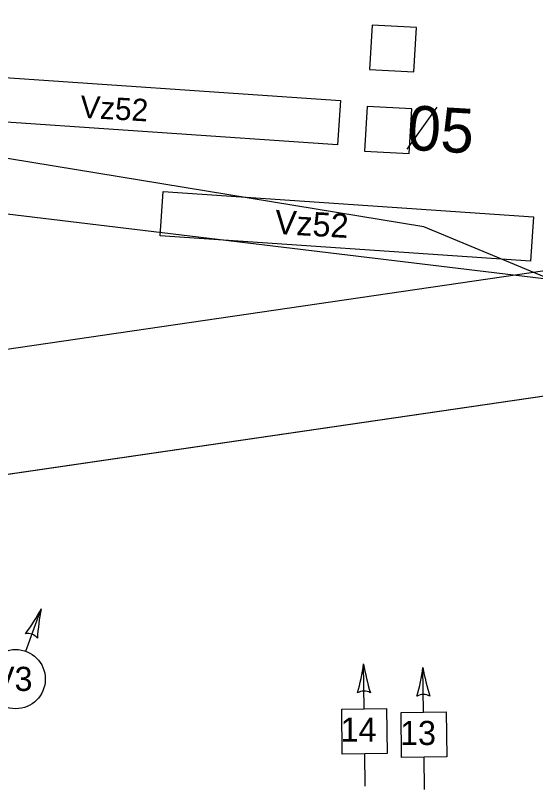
# Model space of a CAD drawing. Extents: x 647787 to 668496, y 640478 to 654412.
# Drawn here: x 661919.8 to 661989.9, y 647240.6 to 647344.9 of the extents above; entities that cross this region are included whole.
import ezdxf

# ---------------------------------------------------------------- set-up
doc = ezdxf.new("R2010")
doc.units = 0
for name, color, linetype in [('Default', 7, 'Continuous'), ('TEMP_DETECTION ZONE', 7, 'Continuous'), ('TEMP_DETECTION_ZONE_STAGE 5', 7, 'Continuous'), ('TEMP_SIGNAL_HEAD_STAGE 2', 7, 'Continuous'), ('TEMP_SIGNAL_POLES_STAGE 1B', 7, 'Continuous'), ('TEXT_TEMP_SIGNAL_POLES_STAGE 2', 7, 'Continuous')]:
    doc.layers.add(name, color=color, linetype=linetype)

msp = doc.modelspace()

# ---------------------------------------------------------------- linework, layer by layer
at = {"layer": 'Default'}
msp.add_line((661972.57, 647326.95), (661976.61, 647332.61), dxfattribs=at)
for points in [[(661974.83, 647316.48), (661742.97, 647354.55)], [(662193.11, 647333.04), (662139.14, 647248.2), (661974.83, 647316.48)], [(662136.44, 647331.77), (661882.02, 647294.61), (661114.4, 647320.89)], [(662008.15, 647307.38), (661891.05, 647321.5)], [(662008.15, 647307.38), (661891.05, 647321.5)], [(662008.15, 647307.38), (661891.05, 647321.5)], [(662108.29, 647310.77), (661853.87, 647273.61), (661086.25, 647299.89)], [(662108.29, 647310.77), (661888.55, 647278.68)], [(662108.29, 647310.77), (661888.55, 647278.68)]]:
    msp.add_lwpolyline(points, dxfattribs=at)
at = {"layer": 'TEMP_DETECTION ZONE'}
for points in [[(661967.86, 647343.64), (661967.5, 647337.65), (661973.5, 647337.34), (661973.86, 647343.33)], [(661967.86, 647343.64), (661967.5, 647337.65), (661973.5, 647337.34), (661973.86, 647343.33)], [(661967.2, 647332.66), (661966.84, 647326.67), (661972.83, 647326.36), (661973.19, 647332.35)], [(661967.2, 647332.66), (661966.84, 647326.67), (661972.83, 647326.36), (661973.19, 647332.35)]]:
    msp.add_lwpolyline(points, close=True, dxfattribs=at)
at = {"layer": 'TEMP_DETECTION_ZONE_STAGE 5'}
msp.add_lwpolyline([(661913.31, 647330.91), (661913.72, 647336.89), (661963.6, 647333.48), (661963.19, 647327.5)], close=True, dxfattribs=at)
at = {"layer": 'TEMP_SIGNAL_HEAD_STAGE 2'}
for p, q in [((661921.2, 647259.28), (661923.28, 647264.98)), ((661966.79, 647251.52), (661966.71, 647257.56)), ((661974.8, 647251.05), (661974.71, 647257.09)), ((661966.93, 647241.11), (661966.87, 647245.46)), ((661974.93, 647240.65), (661974.88, 647244.99))]:
    msp.add_line(p, q, dxfattribs=at)
for points in [[(661969.9, 647245.5), (661963.84, 647245.42), (661963.76, 647251.48), (661969.82, 647251.56)], [(661977.91, 647245.03), (661971.84, 647244.95), (661971.76, 647251.01), (661977.83, 647251.1)]]:
    msp.add_lwpolyline(points, close=True, dxfattribs=at)
msp.add_circle((661919.82, 647255.52), 4, dxfattribs=at)
for centre, radius, start, end in [((661897.42, 647279.11), 29.47, 323.6033, 331.3414), ((661952.16, 647259.13), 29.47, 168.5589, 176.297), ((661921.47, 647260.03), 1.63, 38.0923, 101.7869), ((661937.51, 647261.58), 29.47, 344.421, 352.1591), ((661995.79, 647262.36), 29.47, 189.3758, 197.1139), ((661945.52, 647261.12), 29.47, 344.421, 352.1591), ((662003.79, 647261.9), 29.47, 189.3758, 197.1139), ((661966.78, 647252.29), 1.63, 58.9201, 122.6148), ((661974.79, 647251.83), 1.63, 58.9201, 122.6148)]:
    msp.add_arc(centre, radius, start, end, dxfattribs=at)
at = {"layer": 'TEMP_SIGNAL_POLES_STAGE 1B'}
msp.add_lwpolyline([(661939.3, 647315.26), (661939.71, 647321.24), (661989.59, 647317.83), (661989.18, 647311.85)], close=True, dxfattribs=at)

# ---------------------------------------------------------------- texts
at = {"layer": 'Default'}
msp.add_text('05', height=6, rotation=356.6181, dxfattribs=at).set_placement((661972.5, 647326.87))
at = {"layer": 'TEMP_DETECTION_ZONE_STAGE 5'}
msp.add_text('Vz52', height=3, rotation=356.7697, dxfattribs=at).set_placement((661928.47, 647331.18))
at = {"layer": 'TEMP_SIGNAL_POLES_STAGE 1B'}
msp.add_text('Vz52', height=3.25, rotation=356.7697, dxfattribs=at).set_placement((661954.7, 647315.52))
at = {"layer": 'TEXT_TEMP_SIGNAL_POLES_STAGE 2'}
for s, p in [('V3', (661916.78, 647253.93)), ('14', (661963.62, 647247.1)), ('13', (661971.63, 647246.64))]:
    msp.add_text(s, height=3.25, dxfattribs=at).set_placement(p)

doc.saveas('drawing.dxf')
